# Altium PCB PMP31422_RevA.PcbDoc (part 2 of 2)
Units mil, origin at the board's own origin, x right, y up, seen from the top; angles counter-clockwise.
Board outline 5850 x 1977.34 mil, 2 copper layers (Top Layer, Bottom Layer), stack 62 mil thick; 70 components, 36 nets, 149 pads, 18 vias.
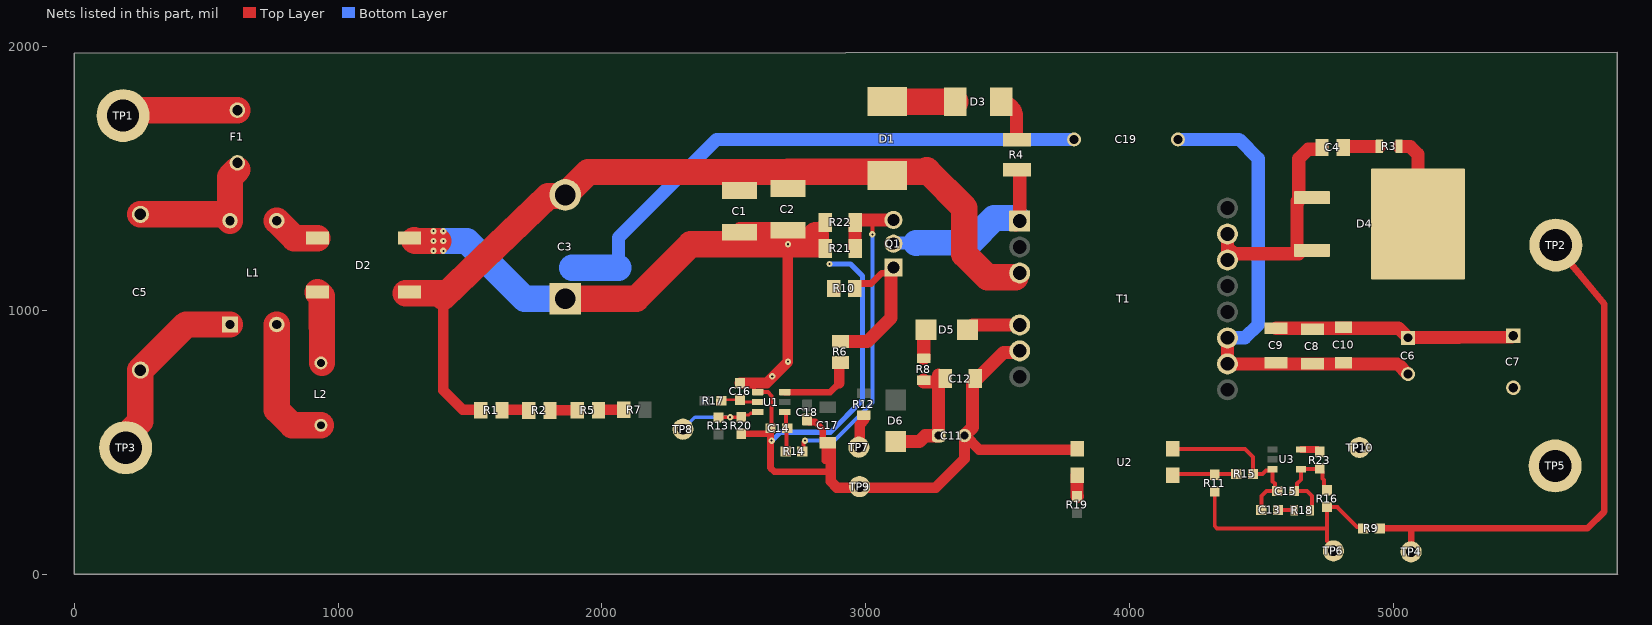
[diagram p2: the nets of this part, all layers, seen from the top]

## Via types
v1: diameter 24, hole 7.87, Top Layer to Bottom Layer, tented both sides, 10 vias
v2: diameter 24, hole 8, Top Layer to Bottom Layer, tented both sides, 8 vias

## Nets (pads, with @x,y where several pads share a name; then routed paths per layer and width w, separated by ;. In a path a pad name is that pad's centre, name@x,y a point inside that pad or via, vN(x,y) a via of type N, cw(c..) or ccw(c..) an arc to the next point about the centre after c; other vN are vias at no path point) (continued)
GND: C6.2 C7.2 C8.2 C9.2 C10.2 C19.1 R23.2 T1.8 T1.9 TP5.1 TP10.1 U3.5 | length 1975.4
  Top Layer w25: U3.5@4650.08,472.14 4712.67,472.14 4720.83,463.98 R23.2@4720.83,463
  Top Layer w50: T1.9@4371.01,895.14 T1.8@4371.01,796.72 5016.06,796.72 5055.01,757.77 C6.2@5055.86,757.77
  Bottom Layer w50: C19.1@4183.45,1647.53 4414.97,1647.53 4487.5,1575 4487.5,945.56 4437.5,895.56 4371.43,895.56 T1.9@4371.01,895.14
NetC1_1: C1.1 C2.1 C3.2 D1.2 D2.1 R1.2 T1.3 | length 3345.6
  Top Layer w40: 1397.42,1067.91 1398.71,696.95 1472.77,622.89 R1.2@1540.33,622.89
  Top Layer w50: C1.1@2521.46,1453.83 2541.1,1453.83 C1.1@2547.59,1460.32
  Top Layer w100: D2.1@1256.25,1065.01 1391.9,1065.01 ; 1397.48,1049.97 1796.22,1433.24 1857.26,1433.24 1947.78,1523.76 2704.93,1524.78 3081.3,1525.29 3236.5,1525.5 ; 3231.22,1530.77 3373.71,1387.5 3373.71,1212.5 3461.21,1125 T1.3@3567.4,1125
NetC4_1: C4.1 R3.1 | length 140.9
  Top Layer w50: C4.1@4810.03,1617 4810.03,1621.14 R3.1@4946.8,1621.14
NetC4_2: C4.2 D4.1 D4.3 T1.12 T1.13 | length 858.7
  Top Layer w50: T1.12@4371.01,1190.42 4371.01,1239.63 ; T1.13@4371.01,1288.84 4371.01,1239.63 ; D4.3@4641.67,1214.43 D4.3@4635.46,1214.43 ; D4.1@4641.67,1414.43 D4.1@4635.46,1414.43 ; C4.2@4730.03,1617 4730.03,1610.5 4677.17,1610.5 4641.67,1575 4641.67,1420.63 D4.1@4635.46,1414.43 ; 4371.01,1239.63 4396.22,1214.43 D4.3@4635.46,1214.43 ; D4.3@4635.46,1214.43 4635.21,1214.68 4635.21,1414.17 D4.1@4635.46,1414.43
NetC5_1: C5.1 F1.1 L1.4 | length 554.8
  Top Layer w100: C5.1@250.24,1363.43 565.98,1363.43 L1.4@589.74,1339.67 589.74,1505.11 F1.1@618.02,1533.38
NetC5_2: C5.2 L1.1 TP3.1 | length 674.7
  Top Layer w100: TP3.1@200.72,529.93 250.24,579.46 C5.2@250.24,772.88 423.33,945.96 L1.1@589.74,945.96
NetC6_1: C6.1 C7.1 C8.1 C9.1 C10.1 D4.2 R3.2 R9.2 TP2.1 TP4.1 | length 3297.2
  Top Layer w25: R9.2@4948.19,172.82 5062.5,172.82 ; TP4.1@5067.09,84.27 5067.09,168.23 5062.5,172.82 ; TP2.1@5617.84,1242.17 5800,1022.33 5800,237.5 5735.32,172.82 5062.5,172.82
  Top Layer w50: C9.1@4555.57,931.45 5019.97,931.45 C6.1@5055.86,895.56 C7.1@5450.18,898.6 ; R3.2@5021.6,1621.14 5022.19,1620.55 5063.96,1620.55 5093.25,1591.26 D4.2@5093.25,1326.93
NetC11_1: C11.1 C12.2 D6.2 R8.1 | length 498.7
  Top Layer w50: D6.2@3113.93,502.11 3202.93,502.11 3225.32,524.5 3275.21,524.5 C11.1@3275.8,525.09 ; R8.1@3219.37,734.66 3219.37,727.97 3219.96,727.38 3263.18,727.38 3275.11,715.44 3275.11,750.33 ; C11.1@3275.91,528.54 3276.02,740.94 C12.2@3276.03,753.37
NetC13_1: C13.1 C15.1 R15.1 U2.2 U3.3 | length 679.1
  Top Layer w15: U2.2@4163.96,474.56 4437.5,474.56 4467.82,444.25 R15.1@4467.82,379.35 ; R15.1@4471.29,375.88 R15.1@4467.82,379.35 ; C13.1@4499.88,243.36 4499.88,295.39 4518.67,314.18 C15.1@4560.25,314.18 4551.46,322.97 4551.46,342.72 4550.6,342.72 4541.82,351.51 U3.3@4541.82,397.34 4537.51,393.03 4517.39,393.03 4503.71,379.35 R15.1@4467.82,379.35
NetC13_2: C13.2 R18.1 | length 62.5
  Top Layer w15: C13.2@4562.87,243.36 4563.77,242.47 4623.77,242.47 R18.1@4624.66,241.57
NetC14_1: C14.1 R14.2 U1.4 | length 158.6
  Top Layer w15: U1.4@2693.15,614.67 2693.24,614.67 2697.55,610.36 2697.55,556.89 C14.1@2701.95,552.48 ; R14.2@2696.64,465.04 2699.3,467.7 2699.3,549.83 C14.1@2701.95,552.48 ; C14.1@2704.1,550.34 C14.1@2701.95,552.48
NetC15_2: C15.2 R16.1 R18.2 R23.1 U3.4 | length 393.7
  Top Layer w15: C15.2@4623.24,314.18 C15.2@4624.23,314.18 ; R18.2@4683.72,241.57 4690.98,248.84 4690.98,282.28 4691.67,282.97 4691.67,295.39 4672.88,314.18 C15.2@4624.23,314.18 ; R16.1@4748.71,316.93 4737.51,328.13 4737.51,355.77 4732.03,361.26 4732.03,388.81 R23.1@4720.83,400.01 4719.49,398.67 4651.42,398.67 U3.4@4650.08,397.34 4650.08,357.35 4635.43,342.69 4635.43,325.38 C15.2@4624.23,314.18
NetC16_1: C16.1 R17.1 U1.2 | length 143.9
  Top Layer w10: R17.1@2452.61,656.71 2457.14,661.24 C16.1@2523.18,661.24 2532.35,652.07 U1.2@2590.78,652.07
NetD1_1: D1.1 D3.1 | length 258
  Top Layer w100: D1.1@3081.3,1791.26 3081.3,1790.97 D3.1@3338.97,1790.97
NetD2_3: D2.3 L1.3 | length 182.1
  Top Layer w100: L1.3@766.91,1339.67 833.14,1273.44 D2.3@921.61,1273.44
NetD2_4: D2.4 L2.2 | length 275.3
  Top Layer w100: D2.4@921.61,1068.72 938.02,1052.31 L2.2@938.54,800.22
NetD3_2: D3.2 R4.2 | length 167.4
  Top Layer w50: D3.2@3512.98,1790.97 cw(c3512.98,1732.14) 3571.81,1732.14 R4.2@3571.81,1657.17
NetD5_1: D5.1 R8.2 | length 124.4
  Top Layer w50: R8.2@3219.37,817.34 3219.96,817.93 3219.96,930.19 D5.1@3227.94,938.18
NetD5_2: D5.2 T1.4 | length 179
  Top Layer w50: D5.2@3404.87,943.77 3405.16,944.07 3583.32,944.07 T1.4@3583.61,944.36
NetF1_2: F1.2 TP1.1 | length 442.1
  Top Layer w100: TP1.1@184.35,1737.92 204.81,1758.38 F1.2@618.02,1758.38
NetL1_2: L1.2 L2.1 | length 515.4
  Top Layer w100: L1.2@766.91,945.96 766.91,622.47 825.49,563.89 L2.1@934.52,563.89
NetQ1_1: Q1.1 R6.2 R10.2 | length 593.5
  Top Layer w25: R10.2@2958.41,1082.52 2958.41,1088.97 2970.91,1101.47 3020.91,1101.47 3059.82,1140.38 3082.79,1140.38 3095.29,1152.88 Q1.1@3104.74,1162.33
  Top Layer w50: R6.2@2904.09,881.95 3006.95,881.95 3095.29,970.29 Q1.1@3095.29,1152.88
NetQ1_2: Q1.2 R4.1 T1.1 | length 711.3
  Top Layer w50: T1.1@3568.85,1323.29 T1.1@3583.61,1338.06 ; T1.1@3582.75,1338.91 T1.1@3583.61,1338.06 ; R4.1@3583.61,1526.74 T1.1@3583.61,1338.06
  Bottom Layer w50: Q1.2@3104.26,1254.92 3185.74,1254.92
  Bottom Layer w100: 3190.87,1254.81 3354.04,1256.77 3394.76,1257.26 3486.97,1349.47 3535.82,1349.82 3536.18,1349.83 T1.1@3571.67,1349.83
NetQ1_3: Q1.3 R14.1 R21.2 R22.2 | length 1327.5
  Top Layer w15: R14.1@2759.63,465.04 2764.53,469.94 2764.53,500.82 v1(2769.36,505.64) ; v1(3025,1287.5) 3025,1342.33
  Top Layer w50: R21.2@2959.67,1234.09 R22.2@2959.67,1333.01 ; R22.2@2960.22,1338.71 2959.63,1338.12 R22.2@2959.63,1332.97 ; Q1.3@3101.12,1338.71 Q1.3@3104.74,1342.33 3025,1342.33 R22.2@2968.99,1342.33 ; R22.2@2959.63,1332.97 cw(c2968.99,1332.97) R22.2@2968.99,1342.33 ; R22.2@2959.67,1333.01 cw(c2968.99,1333.01) R22.2@2968.99,1342.33
  Bottom Layer w15: v1(2769.36,505.64) 2880.64,505.64 3025,650 v1(3025,1287.5)
NetR1_1: R1.1 R2.2 | length 86.2
  Top Layer w40: R1.1@1620.33,622.89 R2.2@1706.57,622.48
NetR2_1: R2.1 R5.2 | length 92.8
  Top Layer w40: R2.1@1804.01,621.06 1804.73,620.34 1895.51,620.34 R5.2@1896.23,619.63
NetR5_1: R5.1 R7.2 | length 97.1
  Top Layer w40: R5.1@1986.51,621.32 1987.1,621.91 2081.2,621.91 2081.69,621.42 R7.2@2082.76,622.5
NetR6_1: R6.1 U1.6 | length 300.7
  Top Layer w25: U1.6@2693.15,689.47 2865.24,689.47 2900,724.23
  Top Layer w40: 2900,724.23 2900,797.86 R6.1@2904.09,801.95
NetR9_1: R9.1 R11.1 R16.2 TP6.1 | length 921.3
  Top Layer w15: R11.1@4322.88,312.89 4322.88,181.61 4331.66,172.82 4748.71,172.82 ; R16.2@4758.72,243.93 R16.2@4748.71,253.94 ; TP6.1@4772.83,87.67 4772.83,100.88 4748.71,125 4748.71,172.82 ; R9.1@4885.2,172.82 4879.14,178.89 4862.41,178.89 4862.41,178.97 4792.53,248.84 4787.44,253.94 R16.2@4748.71,253.94 ; 4748.71,172.82 4748.71,195.77 4748.71,202.6 R16.2@4748.71,253.94
NetR11_2: R11.2 R15.2 U2.1 | length 243.8
  Top Layer w15: U2.1@4162.98,374.56 4167.76,379.35 R15.2@4404.83,379.35
NetR12_1: R12.1 TP7.1 | length 109.7
  Top Layer w40: TP7.1@2973.59,480.76 2976.68,483.84 2976.68,566.23 ; 2979.76,568.51 R12.1@2994.54,586.01
NetR13_1: R13.1 R20.2 TP8.1 U1.3 | length 359.5
  Top Layer w10: R13.1@2427.86,598.23 R13.1@2428.84,598.23
  Top Layer w12: R13.1@2441.65,593.52 2442.33,594.19 v1(2486.03,594.19) R20.2@2528.08,594.19 ; R20.2@2526.06,596.22 R20.2@2528.08,594.19 ; U1.3@2590.78,614.67 2585.8,609.69 2563.64,609.69 2556.62,602.67 2536.56,602.67 R20.2@2528.08,594.19
  Bottom Layer w12: TP8.1@2307,548.99 2352.2,594.19 v1(2486.03,594.19)
NetR19_1: R19.1 U2.4 | length 80
  Top Layer w50: U2.4@3800.77,374.56 3800.77,295.39 R19.1@3801.39,294.77
PGND: C1.2 C2.2 C3.1 C11.2 C12.1 C14.2 C16.2 C17.2 C18.2 C19.2 D2.2 R10.1 R20.1 R21.1 R22.1 T1.5 TP9.1 U1.1 U2.3 | length 8555.7
  Top Layer w15: 2567.84,724.23 2576.63,715.44 2576.63,693.79 2580.94,689.47 U1.1@2590.78,689.47 2628.9,689.47 2643.37,675 2643.37,556.89 C14.2@2638.96,552.48
  Top Layer w20: C18.2@2771.73,579.9 C18.2@2777.74,585.9
  Top Layer w25: R20.1@2528.08,531.2 2631.7,531.2 2638.96,523.94 ; C14.2@2638.96,552.48 2638.96,523.94 ; C18.2@2777.74,585.9 2777.74,582.6 2784.1,576.24 2809.03,576.24 2836.32,548.94 2836.32,506.78 2843.82,499.28 2843.82,428.82 ; 2869.32,387.5 2653.61,387.5 2638.96,402.14 2638.96,523.94
  Top Layer w40: C16.2@2523.18,724.23 2567.84,724.23 2624.12,724.23 v2(2704.98,805.09) 2704.98,1217.1 2737.88,1250 ; C17.2@2843.82,499.28 C17.2@2855.32,497.63 2865.16,497.63 2866.81,495.97 2866.81,351.26 2890.24,327.83 3265.33,327.83 3374.23,436.73 C11.2@3374.23,525.09 3377.25,525.09 3430.8,471.54 U2.3@3796.17,471.54
  Top Layer w50: C1.2@2486.03,1296.35 C1.2@2521.46,1296.35 ; C1.2@2521.92,1308.85 C2.2@2679.98,1308.85 ; C2.2@2771.73,1283.85 2807.16,1283.85 2845.45,1322.14 R22.1@2845.45,1332.97 ; C11.2@3374.23,525.09 3374.23,525.41 3404.87,556.05 3404.87,722.77 3522.38,840.28 3577.96,840.28 T1.5@3583.61,845.93
  Top Layer w100: D2.2@1288.9,1265.84 1292.24,1262.5 1379.96,1262.5 ; C3.1@1861.1,1043.38 2129.59,1043.38 2336.21,1250 2737.88,1250 2810.06,1250 2810.04,1283.87
  Bottom Layer w20: v1@2645.22,505.64 2645.22,506.41 2646.45,507.64 2647.22,507.64 2677.08,537.5 2865.66,537.5 2987.5,659.34 2987.5,1129.93 2942.43,1175 v1(2862.39,1175)
  Bottom Layer w50: 2062.5,1160.54 2062.5,1275.24 2434.79,1647.53 C19.2@3789.75,1647.53
  Bottom Layer w100: v1(1361.21,1262.5) v2(1398.71,1262.5) 1487.5,1262.5 1706.62,1043.38 C3.1@1861.1,1043.38 ; 1887.5,1160.54 2062.5,1160.54
  other v1: 2643.37,505.64
  other v2: 2645.33,749.34 1361.21,1225 1398.71,1225 2704.98,1250 1361.21,1300 1398.71,1300
pads on no net: T1.2 T1.6 T1.7 T1.10 T1.11 T1.14 U3.1 U3.2

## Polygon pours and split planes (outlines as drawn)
GND on Top Layer "TOP_LAYER_GND_P013" (solid, remove dead copper, pour order 13): 4266.22,764.34 4266.22,914.23 cw(c4287.5,914.23) 4287.5,935.51 4414.49,935.51 cw(c4414.49,912.5) 4437.5,912.5 4437.5,844.71 ccw(c4457.21,844.71) 4457.21,825 5796.72,825 cw(c5796.72,796.72) 5825,796.72 5825,47.92 cw(c5789.58,47.92) 5789.58,12.5 4325,12.5 cw(c4325,62.5) 4275,62.5
NetC6_1 on Top Layer "TOP_LAYER_NETC6_1_P012" (solid, remove dead copper, pour order 12): 4509.47,862.5 cw(c4509.47,898.6) 4473.37,898.6 4473.37,1004.7 cw(c4518.67,1004.7) 4518.67,1050 4822.76,1050 ccw(c4822.76,1112.5) 4885.26,1112.5 4885.26,1535.26 cw(c4912.5,1535.26) 4912.5,1562.5 5787.5,1562.5 cw(c5787.5,1525) 5825,1525 5825,912.5 cw(c5775,912.5) 5775,862.5
NetC4_2 on Top Layer "TOP_LAYER_NETC4_2_P009" (solid, remove dead copper, pour order 9): 4337.5,1162.5 cw(c4337.5,1175) 4325,1175 4325,1314.43 cw(c4337.5,1314.43) 4337.5,1326.93 4576.93,1326.93 ccw(c4576.93,1350) 4600,1350 4600,1427.29 cw(c4635.21,1427.29) 4635.21,1462.5 4737.5,1462.5 cw(c4737.5,1437.5) 4762.5,1437.5 4762.5,1200 cw(c4725,1200) 4725,1162.5
NetQ1_3 on Top Layer "TOP_LAYER_NETQ1_3_P007" (solid, remove dead copper, pour order 7): 2921.4,1196.03 ccw(c2942.89,1196.03) 2942.89,1174.53 3011.36,1174.53 ccw(c3011.36,1194.67) 3031.5,1194.67 3031.5,1287.25 cw(c3052.87,1287.25) 3052.87,1308.62 3121.06,1308.62 ccw(c3121.06,1338.06) 3150.5,1338.06 3150.5,1349.62 ccw(c3113.93,1349.62) 3113.93,1386.19 2939.18,1386.19 ccw(c2939.18,1368.4) 2921.4,1368.4
PGND on Top Layer "TOP_LAYER_PGND_P005" (solid, remove dead copper, pour order 5): 2362.5,780.43 cw(c2400,780.43) 2400,817.93 3428.03,817.93 ccw(c3428.03,845.93) 3456.03,845.93 cw(c3492.06,845.93) 3492.06,881.95 3605.55,881.95 cw(c3605.55,850) 3637.5,850 3637.5,225 cw(c3600,225) 3600,187.5 2462.5,187.5 cw(c2462.5,287.5) 2362.5,287.5 2362.5,300
NetD1_1 on Top Layer "TOP_LAYER_NETD1_1_P004" (solid, remove dead copper, pour order 4): 3398.71,1762.5 3398.71,1850 ccw(c3348.71,1850) 3348.71,1900 2836.52,1900 ccw(c2836.52,1864.16) 2800.68,1864.16 2800.68,1760.56 ccw(c2829.1,1760.56) 2829.1,1732.14 3368.35,1732.14 ccw(c3368.35,1762.5)
NetD3_2 on Top Layer "TOP_LAYER_NETD3_2_P003" (solid, remove dead copper, pour order 3): 3448.71,1850 3448.71,1632.39 ccw(c3473.71,1632.39) 3473.71,1607.39 3646.72,1607.39 ccw(c3646.72,1621.88) 3661.21,1621.88 3661.21,1850 ccw(c3636.21,1850) 3636.21,1875 3473.71,1875 ccw(c3473.71,1850)
PGND on Top Layer "TOP_LAYER_PGND_P002" (solid, remove dead copper, pour order 2): 1863.86,937.5 1773.1,937.5 cw(c1773.1,981.4) 1729.2,981.4 1729.2,1068.17 cw(c1782.76,1068.17) 1782.76,1121.73 2063.81,1121.73 ccw(c2063.81,1187.5) 2129.59,1187.5 2129.59,1238.84 cw(c2223.71,1238.84) 2223.71,1332.97 2832.15,1332.97 cw(c2832.15,1286.71) 2878.41,1286.71 2878.41,1079.7 cw(c2823.71,1079.7) 2823.71,1025 2633.11,1025 ccw(c2633.11,987.5) 2595.61,987.5 cw(c2552.18,987.5) 2552.18,944.07 2486.03,944.07
NetC1_1 on Top Layer "TOP_LAYER_NETC1_1_P000" (solid, remove dead copper, pour order 0): 1773.71,1436.29 1773.71,1575 cw(c1873.71,1575) 1873.71,1675 3211.21,1675 cw(c3211.21,1600) 3286.21,1600 3286.21,1474.71 cw(c3236.5,1474.71) 3236.5,1425 1785,1425 cw(c1785,1436.29)
GND on Bottom Layer "BOTTOM_LAYER_GND_P014" (solid, remove dead copper, pour order 14): 4337.5,1850 cw(c4412.5,1850) 4412.5,1925 5775,1925 cw(c5775,1875) 5825,1875 5825,72.87 cw(c5775,72.87) 5775,22.87 4414.63,22.87 cw(c4414.63,100) 4337.5,100
PGND on Bottom Layer "BOTTOM_LAYER_PGND_P006" (solid, remove dead copper, pour order 6): 1925,100 cw(c1925,187.5) 1837.5,187.5 1837.5,1113.17 cw(c1937.5,1113.17) 1937.5,1213.17 2949.83,1213.17 cw(c2964.22,1146.14) 3031.25,1160.54 3031.25,944.36 ccw(c3115.58,966.28) 3137.5,881.95 3630.55,881.95 cw(c3630.55,837.5) 3675,837.5 3675,162.5 cw(c3612.5,162.5) 3612.5,100

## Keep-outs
Keep-Out Layer:
  text ".Layer_Name" at 577,-858.49 h60

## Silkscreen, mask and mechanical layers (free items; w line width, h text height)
Top Overlay:
  text "'.PRJ_Number'.PCB_Rev" at 2195,125.77 h108.27
  text ".Layer_Name" at 577,-858.49 h60
Bottom Overlay:
  text ".Layer_Name" at 577,-858.49 h60
Top Paste:
  text ".Layer_Name" at 577,-858.49 h60
Bottom Paste:
  text ".Layer_Name" at 577,-858.49 h60
Top Solder:
  text ".Layer_Name" at 577,-858.49 h60
  text ".Layer_Name" at 577,-858.49 h60
Bottom Solder:
  text ".Layer_Name" at 577,-858.49 h60
Drill Guide:
  text ".Layer_Name" at 577,-858.49 h60
M1 Board Outline:
  lines w10: 5847.86,0.02 5847.86,1976.18 ; 5847.86,1977.34 0,1975 0,0 5850,0
  text ".Layer_Name" at 577,-858.49 h60
M2 Board Dimensions:
  rectangle: 125,-400 500,-275
  rectangle: 0,-275 125,-150
  lines w7: 0,-275 1000,-275 ; 125,-400 125,-150 ; 250,-400 250,-150 ; 500,-400 500,-150 ; 750,-400 750,-150 ; 0,-400 0,-150 1000,-150 1000,-400 0,-400
  text ".Layer_Name" at 577,-858.49 h60
M3 3D STEP Top:
  text ".Layer_Name" at 577,-858.49 h60
M4 3D STEP Bottom:
  text ".Layer_Name" at 577,-858.49 h60
M5 Assembly Top:
  lines w10: -292,-930.17 6308,-930.17 ; -292,-726.83 6310,-726.83 ; -292,-523.5 -292,-1133.5 3713,-1133.5 6310,-1133.5 6310,-523.5 -291.5,-523.5 -291.5,-1133.5 1284,-1133.5 ; 2173,-1133.5 2173,-523.5 ; 3440,-726.83 3440,-523.5 ; 4280,-726.83 4280,-523.5 ; 4902,-1140 4902,-937.17
  text "COMPONENTS MARKED 'DNP' SHOULD NOT BE POPULATED." at 1153.5,-318.5 h60
  text "ASSEMBLY VARIANT:" at 1153,-434 h60
  text ".VariantName" at 2189,-434 h60
  text "PCB VIEWED FROM TOP SIDE" at -228.5,-655.67 h60
  text "BOARD #:" at 2248,-655.67 h60
  text ".PRJ_Number" at 2793.5,-655.67 h60
  text "REV:" at 3638,-655.67 h60
  text ".PCB_Rev" at 3929.5,-655.67 h60
  text "SVN REV:" at 4476,-655.67 h60
  text ".VersionControl_RevNumber" at 4982,-655.67 h60
  text "PLOT NAME =" at -228.5,-1064.34 h60
  text ".plot_File_Name" at 577,-1064.34 h60
  text "GENERATED    :" at 2250,-1064.34 h60
  text ".Print_Date" at 3119.5,-1064.34 h60
  text ".Print_Time" at 3848.5,-1064.34 h60
  text "TEXAS INSTRUMENTS" at 5113,-1064.34 h60
M6 Assembly Bottom:
  lines w10: -292.5,-727.33 6309.5,-727.33 ; -290.5,-930.67 6309.5,-930.67 ; 1115.5,-1140.5 1115.5,-937.67 ; 1737.5,-727.33 1737.5,-524 ; 2577.5,-727.33 2577.5,-524 ; 3844.5,-1134 3844.5,-524 ; 4733.5,-1134 6309,-1134 6309,-524 -292.5,-524 -292.5,-1134 2304.5,-1134 6309.5,-1134 6309.5,-524
  text "COMPONENTS MARKED 'DNP' SHOULD NOT BE POPULATED." at 6102,-318 h60
  text ".VariantName" at 5058,-434 h60
  text "ASSEMBLY VARIANT:" at 6097,-434 h60
  text ".VersionControl_RevNumber" at 1035.5,-656.17 h60
  text "SVN REV:" at 1541.5,-656.17 h60
  text ".PCB_Rev" at 2088,-656.17 h60
  text "REV:" at 2379.5,-656.17 h60
  text ".PRJ_Number" at 3224,-656.17 h60
  text "BOARD #:" at 3769.5,-656.17 h60
  text "PCB VIEWED FROM BOTTOM SIDE" at 6246,-656.17 h60
  text "TEXAS INSTRUMENTS" at 904.5,-1064.84 h60
  text ".Print_Time" at 2169,-1064.84 h60
  text ".Print_Date" at 2898,-1064.84 h60
  text "GENERATED    :" at 3767.5,-1064.84 h60
  text ".plot_File_Name" at 5440.5,-1064.84 h60
  text "PLOT NAME =" at 6246,-1064.84 h60
M9 Title Sheet:
  drawing of 56 lines, arcs and shapes, not listed
  text "1" at 1058.34,13381.39 h70
  text "2" at 4384,13381.39 h70
  text "3" at 7714,13381.39 h70
  text "4" at 11049,13381.39 h70
  text "5" at 14374,13381.39 h70
  text "6" at 17709,13381.39 h70
  text "A" at -463,11603.39 h70
  text "A" at 19237,11603.39 h70
  text "B" at -463,7853.39 h70
  text "B" at 19237,7853.39 h70
  text "C" at -463,4103.39 h70
  text "C" at 19237,4103.39 h70
  text "D" at -463,353.39 h70
  text "D" at 19237,353.39 h70
  text "PROJECT TITLE:" at 16143,268.39 h45
  text ".PRJ_Title" at 16193,135.06 h70
  text "DESIGNED FOR:" at 16143,-32.61 h45
  text ".PRJ_Customer" at 16193,-172.61 h70
  text "FILE NAME:" at 16143,-332.61 h45
  text ".PCB_File_Name_No_Path" at 16193,-452.61 h70
  text "Texas Instruments (TI) and/or its licensors do not warrant the accuracy or completeness of this specification" at 11173.5,-614.45 h45
  text "ENGINEER:" at 16143,-622.61 h45
  text "LAYOUT BY:" at 17648,-622.61 h45
  text "or any information contained therein. TI and/or its licensors do not warrant that this design will meet" at 11128.51,-727.11 h45
  text ".PRJ_Engineer" at 16193,-777.6 h70
  text ".PCB_Layout" at 17698.5,-777.6 h70
  text "the specifications, will be suitable for your application or fit for any particular purpose, or will operate in" at 11128.51,-839.78 h45
  text ".Layer_Name" at 577,-858.49 h60
  text "ALTIUM DESIGNER VERSION:" at 17648,-932.61 h45
  text "an implementation. TI and/or its licensors do not warrant that the design is production worthy. You should" at 11128.51,-952.44 h45
  text "completely validate and test your design implementation to confirm the system functionality for your application." at 11173.5,-1065.11 h45
  text ".print_Scale" at 16193,-1065.94 h70
  text ".Application_BuildNumber" at 17698.5,-1065.94 h70
  text "1" at 1058.34,-1318.61 h70
  text "2" at 4384,-1318.61 h70
  text "3" at 7714,-1318.61 h70
  text "4" at 11049,-1318.61 h70
  text "5" at 14374,-1318.61 h70
  text "6" at 17709,-1318.61 h70
M10 Fab Notes:
  text ".Layer_Name" at 577,-858.49 h60
M11 Gerber Information:
  lines w10: -292,-930.17 6308,-930.17 ; -292,-726.83 6310,-726.83 ; -292,-523.5 -292,-1133.5 3713,-1133.5 6310,-1133.5 6310,-523.5 -291.5,-523.5 -291.5,-1133.5 1284,-1133.5 ; 2173,-1133.5 2173,-523.5 ; 3440,-726.83 3440,-523.5 ; 4280,-726.83 4280,-523.5 ; 4902,-1140 4902,-937.17
  text "ALL ARTWORK VIEWED FROM TOP SIDE" at -228.5,-655.67 h60
  text "BOARD #:" at 2248,-655.67 h60
  text ".PRJ_Number" at 2793.5,-655.67 h60
  text "REV:" at 3638,-655.67 h60
  text ".PCB_Rev" at 3929.5,-655.67 h60
  text "SVN REV:" at 4476,-655.67 h60
  text ".VersionControl_RevNumber" at 4982,-655.67 h60
  text "LAYER NAME =" at -228.5,-858.49 h60
  text "PLOT NAME =" at -228.5,-1064.34 h60
  text ".plot_File_Name" at 577,-1064.34 h60
  text "GENERATED    :" at 2250,-1064.34 h60
  text ".Print_Date" at 3119.5,-1064.34 h60
  text ".Print_Time" at 3848.5,-1064.34 h60
  text "TEXAS INSTRUMENTS" at 5113,-1064.34 h60
M12 Stackup:
  drawing of 191 lines, arcs and shapes, not listed
  text "Layer" at 14605.06,13091.48 h60
  text "Name" at 15014.97,13091.48 h60
  text "Material" at 15944.72,13091.48 h60
  text "Thickness" at 16804.48,13091.48 h60
  text "Constant" at 17454.32,13091.48 h60
  text "Board Layer Stack" at 18024.18,13091.48 h60
  text "Top Overlay" at 15014.97,12971.48 h60
  text "Top Solder" at 15014.97,12851.48 h60
  text "Solder Resist" at 15944.72,12851.48 h60
  text "0.40mil" at 16804.48,12851.48 h60
  text "3.5" at 17454.32,12851.48 h60
  text "1" at 14605.06,12731.48 h60
  text "Top Layer" at 15014.97,12731.48 h60
  text "1.40mil" at 16804.48,12731.48 h60
  text "Dielectric1" at 15014.97,12611.48 h60
  text "FR-4 High Tg" at 15944.72,12611.48 h60
  text "59.20mil" at 16804.48,12611.48 h60
  text "4.8" at 17454.32,12611.48 h60
  text "2" at 14605.06,12491.48 h60
  text "Bottom Layer" at 15014.97,12491.48 h60
  text "1.40mil" at 16804.48,12491.48 h60
  text "Bottom Solder" at 15014.97,12371.48 h60
  text "Solder Resist" at 15944.72,12371.48 h60
  text "0.40mil" at 16804.48,12371.48 h60
  text "3.5" at 17454.32,12371.48 h60
  text "Bottom Overlay" at 15014.97,12251.48 h60
  text ".Layer_Name" at 577,-858.49 h60
M13 Component Bodies Top:
  text ".Layer_Name" at 577,-858.49 h60
M14 Component Bodies Bottom:
  text ".Layer_Name" at 577,-858.49 h60
M15 Courtyards Top:
  text ".Layer_Name" at 577,-858.49 h60
M16 Courtyards Bottom:
  text ".Layer_Name" at 577,-858.49 h60
Drill Drawing:
  circle w10: c5443.72,3159.96 r16.58
  circle w10: c5443.72,3159.96 r27.63
  circle w10: c5443.72,2041.08 r27.63
  lines w10: 5416.09,1778.63 5429.9,1778.63 5443.72,1764.82 5457.53,1778.63 5471.34,1778.63 5457.53,1792.44 5471.34,1806.26 5457.53,1806.26 5443.72,1820.07 5429.9,1806.26 5416.09,1806.26 5429.9,1792.44 5416.09,1778.63 ; 5416.09,1902.95 5429.9,1902.95 5443.72,1889.14 5457.53,1902.95 5471.34,1902.95 5457.53,1916.76 5471.34,1930.58 5457.53,1930.58 5443.72,1944.39 5429.9,1930.58 5416.09,1930.58 5429.9,1916.76 5416.09,1902.95 ; 5416.09,2165.4 5443.72,2137.78 5471.34,2165.4 5443.72,2193.03 5416.09,2165.4 ; 5416.09,2262.1 5443.72,2275.91 5471.34,2262.1 5457.53,2289.72 5471.34,2317.35 5443.72,2303.54 5416.09,2317.35 5429.9,2289.72 5416.09,2262.1 ; 5416.09,2386.42 5471.34,2386.42 5471.34,2441.67 5416.09,2441.67 5416.09,2386.42 ; 5416.09,2565.99 5471.34,2565.99 5443.72,2510.74 5416.09,2565.99 ; 5416.09,2635.06 5443.72,2648.87 5471.34,2635.06 5457.53,2662.68 5471.34,2690.31 5443.72,2676.5 5416.09,2690.31 5429.9,2662.68 5416.09,2635.06 ; 5416.09,2759.38 5416.09,2773.19 5429.9,2787 5416.09,2800.82 5416.09,2814.63 5429.9,2814.63 5443.72,2800.82 5457.53,2814.63 5471.34,2814.63 5471.34,2800.82 5457.53,2787 5471.34,2773.19 5471.34,2759.38 5457.53,2759.38 5443.72,2773.19 5429.9,2759.38 5416.09,2759.38 ; 5416.09,2897.51 5429.9,2897.51 5429.9,2883.7 5457.53,2883.7 5457.53,2897.51 5471.34,2897.51 5471.34,2925.14 5457.53,2925.14 5457.53,2938.95 5429.9,2938.95 5429.9,2925.14 5416.09,2925.14 5416.09,2897.51 ; 5416.09,3063.27 5471.34,3063.27 5443.72,3008.02 5416.09,3063.27 ; 5416.09,3256.66 5471.34,3256.66 5471.34,3311.91 5416.09,3311.91 5416.09,3256.66 ; 5427.14,1784.15 5435.43,1784.15 5443.72,1775.87 5452.01,1784.15 5460.29,1784.15 5452.01,1792.44 5460.29,1800.73 5452.01,1800.73 5443.72,1809.02 5435.43,1800.73 5427.14,1800.73 5435.43,1792.44 5427.14,1784.15 ; 5427.14,2273.15 5443.72,2281.43 5460.29,2273.15 5452.01,2289.72 5460.29,2306.3 5443.72,2298.01 5427.14,2306.3 5435.43,2289.72 5427.14,2273.15 ; 5427.14,3052.22 5460.29,3052.22 5443.72,3019.07 5427.14,3052.22 ; 5427.14,3267.71 5460.29,3267.71 5460.29,3300.86 5427.14,3300.86 5427.14,3267.71
  lines w12: 5366,1727.52 8597.49,1727.52 ; 5366,3343.68 8597.49,3343.68 ; 5703.86,1603.2 5703.86,3468 ; 6035.86,1603.2 6035.86,3468 ; 6672.43,1603.2 6672.43,3468 ; 6931.57,1603.2 6931.57,3468 ; 7306.72,1603.2 7306.72,3468 ; 8031.05,1603.2 8031.05,3468 ; 5366,1603.2 8597.49,1603.2 8597.49,3468 5366,3468 5366,1603.2
  text "Symbol" at 5440.59,3380.98 h72
  text "Quantity" at 5741.16,3380.98 h72
  text "Finished Hole Size" at 6073.16,3380.98 h72
  text "Plated" at 6709.72,3380.98 h72
  text "Hole Type" at 6968.86,3380.98 h72
  text "Drill Layer Pair" at 7344.02,3380.98 h72
  text "Hole Tolerance" at 8068.35,3380.98 h72
  text "10" at 5741.16,3256.66 h60
  text "7.87mil (0.200mm)" at 6073.16,3256.66 h60
  text "PTH" at 6709.72,3256.66 h60
  text "Round" at 6968.86,3256.66 h60
  text "Top Layer - Bottom Layer" at 7344.02,3256.66 h60
  text "8" at 5741.16,3132.34 h60
  text "8.00mil (0.203mm)" at 6073.16,3132.34 h60
  text "PTH" at 6709.72,3132.34 h60
  text "Round" at 6968.86,3132.34 h60
  text "Top Layer - Bottom Layer" at 7344.02,3132.34 h60
  text "2" at 5741.16,3008.02 h60
  text "29.53mil (0.750mm)" at 6073.16,3008.02 h60
  text "PTH" at 6709.72,3008.02 h60
  text "Round" at 6968.86,3008.02 h60
  text "Top Layer - Bottom Layer" at 7344.02,3008.02 h60
  text "2" at 5741.16,2883.7 h60
  text "31.50mil (0.800mm)" at 6073.16,2883.7 h60
  text "PTH" at 6709.72,2883.7 h60
  text "Round" at 6968.86,2883.7 h60
  text "Top Layer - Bottom Layer" at 7344.02,2883.7 h60
  text "4" at 5741.16,2759.38 h60
  text "33.47mil (0.850mm)" at 6073.16,2759.38 h60
  text "PTH" at 6709.72,2759.38 h60
  text "Round" at 6968.86,2759.38 h60
  text "Top Layer - Bottom Layer" at 7344.02,2759.38 h60
  text "6" at 5741.16,2635.06 h60
  text "35.43mil (0.900mm)" at 6073.16,2635.06 h60
  text "PTH" at 6709.72,2635.06 h60
  text "Round" at 6968.86,2635.06 h60
  text "Top Layer - Bottom Layer" at 7344.02,2635.06 h60
  text "2" at 5741.16,2510.74 h60
  text "39.37mil (1.000mm)" at 6073.16,2510.74 h60
  text "PTH" at 6709.72,2510.74 h60
  text "Round" at 6968.86,2510.74 h60
  text "Top Layer - Bottom Layer" at 7344.02,2510.74 h60
  text "6" at 5741.16,2386.42 h60
  text "40.00mil (1.016mm)" at 6073.16,2386.42 h60
  text "PTH" at 6709.72,2386.42 h60
  text "Round" at 6968.86,2386.42 h60
  text "Top Layer - Bottom Layer" at 7344.02,2386.42 h60
  text "2" at 5741.16,2262.1 h60
  text "43.31mil (1.100mm)" at 6073.16,2262.1 h60
  text "PTH" at 6709.72,2262.1 h60
  text "Round" at 6968.86,2262.1 h60
  text "Top Layer - Bottom Layer" at 7344.02,2262.1 h60
  text "3" at 5741.16,2137.78 h60
  text "45.28mil (1.150mm)" at 6073.16,2137.78 h60
  text "PTH" at 6709.72,2137.78 h60
  text "Round" at 6968.86,2137.78 h60
  text "Top Layer - Bottom Layer" at 7344.02,2137.78 h60
  text "14" at 5741.16,2013.46 h60
  text "51.97mil (1.320mm)" at 6073.16,2013.46 h60
  text "PTH" at 6709.72,2013.46 h60
  text "Round" at 6968.86,2013.46 h60
  text "Top Layer - Bottom Layer" at 7344.02,2013.46 h60
  text "2" at 5741.16,1889.14 h60
  text "78.74mil (2.000mm)" at 6073.16,1889.14 h60
  text "PTH" at 6709.72,1889.14 h60
  text "Round" at 6968.86,1889.14 h60
  text "Top Layer - Bottom Layer" at 7344.02,1889.14 h60
  text "4" at 5741.16,1764.82 h60
  text "122.05mil (3.100mm)" at 6073.16,1764.82 h60
  text "PTH" at 6709.72,1764.82 h60
  text "Round" at 6968.86,1764.82 h60
  text "Top Layer - Bottom Layer" at 7344.02,1764.82 h60
  text "65 Total" at 5741.16,1640.5 h60
  text ".Layer_Name" at 577,-858.49 h60
M17 Embedded Cavity:
  text ".Layer_Name" at 577,-858.49 h60
M18 Embedded Assembly:
  text ".Layer_Name" at 577,-858.49 h60
M19 Embedded Keepout:
  text ".Layer_Name" at 567,-858.49 h60

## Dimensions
0,-400 to 1000,-400 on M2 Board Dimensions
0,0 to 5850,0 on M2 Board Dimensions
0,0 to 5847.86,1977.34 on M2 Board Dimensions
